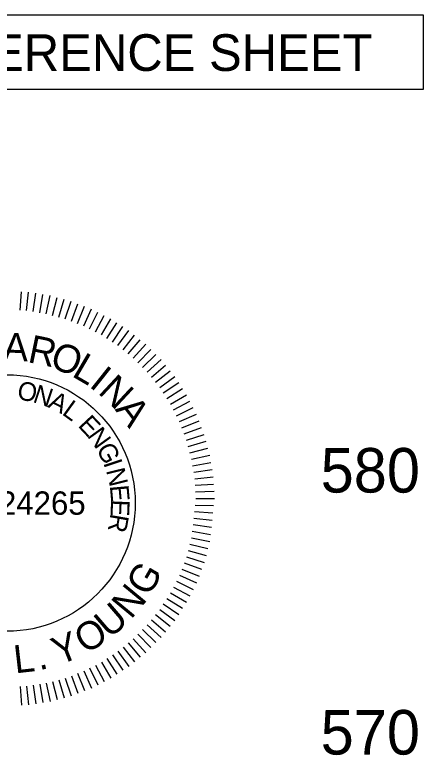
# Model space of a CAD drawing. Extents: x 1964377 to 1966966, y 1116414 to 1123213.
# Drawn here: x 1966872.9 to 1966950.9, y 1122576.7 to 1122718 of the extents above; entities that cross this region are included whole.
import ezdxf

# ---------------------------------------------------------------- set-up
doc = ezdxf.new("R2010")
doc.units = 0
for name, color, linetype in [('RD_DDB_Profile_Elev', 7, 'Continuous'), ('RD_Sketch1', 7, 'Continuous'), ('RD_TX_PEShield', 7, 'Continuous')]:
    doc.layers.add(name, color=color, linetype=linetype)

msp = doc.modelspace()

# ---------------------------------------------------------------- linework, layer by layer
at = {"layer": 'RD_Sketch1'}
msp.add_lwpolyline([(1966650.5, 1122717.98), (1966950.92, 1122717.98), (1966950.92, 1122703.72), (1966650.5, 1122703.72)], close=True, dxfattribs=at)
at = {"layer": 'RD_TX_PEShield'}
for p, q in [((1966873.96, 1122661.59), (1966874.21, 1122665.14)), ((1966873.96, 1122661.59), (1966874.21, 1122665.14)), ((1966875.21, 1122661.52), (1966875.59, 1122665.06)), ((1966875.21, 1122661.52), (1966875.59, 1122665.06)), ((1966876.46, 1122661.33), (1966876.95, 1122664.85)), ((1966876.46, 1122661.33), (1966876.95, 1122664.85)), ((1966877.7, 1122661.13), (1966878.32, 1122664.63)), ((1966877.7, 1122661.13), (1966878.32, 1122664.63)), ((1966878.94, 1122660.93), (1966879.68, 1122664.41)), ((1966878.94, 1122660.93), (1966879.68, 1122664.41)), ((1966878.94, 1122660.93), (1966879.68, 1122664.41)), ((1966880.16, 1122660.61), (1966881.02, 1122664.06)), ((1966880.16, 1122660.61), (1966881.02, 1122664.06)), ((1966880.16, 1122660.61), (1966881.02, 1122664.06)), ((1966881.37, 1122660.28), (1966882.35, 1122663.7)), ((1966881.37, 1122660.28), (1966882.35, 1122663.7)), ((1966881.37, 1122660.28), (1966882.35, 1122663.7)), ((1966882.59, 1122659.96), (1966883.69, 1122663.34)), ((1966882.59, 1122659.96), (1966883.69, 1122663.34)), ((1966882.59, 1122659.96), (1966883.69, 1122663.34)), ((1966883.76, 1122659.51), (1966884.98, 1122662.85)), ((1966883.76, 1122659.51), (1966884.98, 1122662.85)), ((1966883.76, 1122659.51), (1966884.98, 1122662.85)), ((1966884.93, 1122659.06), (1966886.26, 1122662.35)), ((1966884.93, 1122659.06), (1966886.26, 1122662.35)), ((1966884.93, 1122659.06), (1966886.26, 1122662.35)), ((1966886.11, 1122658.6), (1966887.56, 1122661.86)), ((1966886.11, 1122658.6), (1966887.56, 1122661.86)), ((1966886.11, 1122658.6), (1966887.56, 1122661.86)), ((1966887.23, 1122658.03), (1966888.79, 1122661.23)), ((1966887.23, 1122658.03), (1966888.79, 1122661.23)), ((1966887.23, 1122658.03), (1966888.79, 1122661.23)), ((1966888.35, 1122657.46), (1966890.02, 1122660.6)), ((1966888.35, 1122657.46), (1966890.02, 1122660.6)), ((1966888.35, 1122657.46), (1966890.02, 1122660.6)), ((1966889.47, 1122656.89), (1966891.25, 1122659.97)), ((1966889.47, 1122656.89), (1966891.25, 1122659.97)), ((1966889.47, 1122656.89), (1966891.25, 1122659.97)), ((1966890.52, 1122656.21), (1966892.41, 1122659.22)), ((1966890.52, 1122656.21), (1966892.41, 1122659.22)), ((1966890.52, 1122656.21), (1966892.41, 1122659.22)), ((1966891.58, 1122655.52), (1966893.57, 1122658.47)), ((1966891.58, 1122655.52), (1966893.57, 1122658.47)), ((1966891.58, 1122655.52), (1966893.57, 1122658.47)), ((1966892.63, 1122654.84), (1966894.73, 1122657.72)), ((1966892.63, 1122654.84), (1966894.73, 1122657.72)), ((1966892.63, 1122654.84), (1966894.73, 1122657.72)), ((1966893.61, 1122654.04), (1966895.8, 1122656.85)), ((1966893.61, 1122654.04), (1966895.8, 1122656.85)), ((1966893.61, 1122654.04), (1966895.8, 1122656.85)), ((1966894.59, 1122653.25), (1966896.87, 1122655.98)), ((1966894.59, 1122653.25), (1966896.87, 1122655.98)), ((1966894.59, 1122653.25), (1966896.87, 1122655.98)), ((1966895.57, 1122652.46), (1966897.95, 1122655.11)), ((1966895.57, 1122652.46), (1966897.95, 1122655.11)), ((1966895.57, 1122652.46), (1966897.95, 1122655.11)), ((1966896.46, 1122651.57), (1966898.93, 1122654.13)), ((1966896.46, 1122651.57), (1966898.93, 1122654.13)), ((1966896.46, 1122651.57), (1966898.93, 1122654.13)), ((1966897.34, 1122650.68), (1966899.9, 1122653.15)), ((1966897.34, 1122650.68), (1966899.9, 1122653.15)), ((1966897.34, 1122650.68), (1966899.9, 1122653.15)), ((1966898.23, 1122649.79), (1966900.88, 1122652.18)), ((1966898.23, 1122649.79), (1966900.88, 1122652.18)), ((1966898.23, 1122649.79), (1966900.88, 1122652.18)), ((1966899.03, 1122648.82), (1966901.75, 1122651.1)), ((1966899.03, 1122648.82), (1966901.75, 1122651.1)), ((1966899.03, 1122648.82), (1966901.75, 1122651.1)), ((1966899.82, 1122647.84), (1966902.62, 1122650.03)), ((1966899.82, 1122647.84), (1966902.62, 1122650.03)), ((1966899.82, 1122647.84), (1966902.62, 1122650.03)), ((1966900.61, 1122646.86), (1966903.49, 1122648.95)), ((1966900.61, 1122646.86), (1966903.49, 1122648.95)), ((1966900.61, 1122646.86), (1966903.49, 1122648.95)), ((1966901.29, 1122645.81), (1966904.24, 1122647.8)), ((1966901.29, 1122645.81), (1966904.24, 1122647.8)), ((1966901.29, 1122645.81), (1966904.24, 1122647.8)), ((1966901.98, 1122644.75), (1966904.99, 1122646.64)), ((1966901.98, 1122644.75), (1966904.99, 1122646.64)), ((1966901.98, 1122644.75), (1966904.99, 1122646.64)), ((1966902.66, 1122643.7), (1966905.75, 1122645.48)), ((1966902.66, 1122643.7), (1966905.75, 1122645.48)), ((1966902.66, 1122643.7), (1966905.75, 1122645.48)), ((1966903.23, 1122642.58), (1966906.37, 1122644.25)), ((1966903.23, 1122642.58), (1966906.37, 1122644.25)), ((1966903.23, 1122642.58), (1966906.37, 1122644.25)), ((1966903.8, 1122641.46), (1966907, 1122643.02)), ((1966903.8, 1122641.46), (1966907, 1122643.02)), ((1966903.8, 1122641.46), (1966907, 1122643.02)), ((1966904.38, 1122640.34), (1966907.63, 1122641.78)), ((1966904.38, 1122640.34), (1966907.63, 1122641.78)), ((1966904.38, 1122640.34), (1966907.63, 1122641.78)), ((1966904.83, 1122639.16), (1966908.12, 1122640.49)), ((1966904.83, 1122639.16), (1966908.12, 1122640.49)), ((1966904.83, 1122639.16), (1966908.12, 1122640.49)), ((1966905.28, 1122637.99), (1966908.62, 1122639.2)), ((1966905.28, 1122637.99), (1966908.62, 1122639.2)), ((1966905.28, 1122637.99), (1966908.62, 1122639.2)), ((1966905.73, 1122636.81), (1966909.11, 1122637.91)), ((1966905.73, 1122636.81), (1966909.11, 1122637.91)), ((1966905.73, 1122636.81), (1966909.11, 1122637.91)), ((1966906.05, 1122635.6), (1966909.47, 1122636.58)), ((1966906.05, 1122635.6), (1966909.47, 1122636.58)), ((1966906.05, 1122635.6), (1966909.47, 1122636.58)), ((1966906.38, 1122634.38), (1966909.83, 1122635.25)), ((1966906.38, 1122634.38), (1966909.83, 1122635.25)), ((1966906.38, 1122634.38), (1966909.83, 1122635.25)), ((1966906.7, 1122633.17), (1966910.19, 1122633.91)), ((1966906.7, 1122633.17), (1966910.19, 1122633.91)), ((1966906.7, 1122633.17), (1966910.19, 1122633.91)), ((1966906.9, 1122631.93), (1966910.4, 1122632.54)), ((1966906.9, 1122631.93), (1966910.4, 1122632.54)), ((1966906.9, 1122631.93), (1966910.4, 1122632.54)), ((1966907.1, 1122630.69), (1966910.62, 1122631.18)), ((1966907.1, 1122630.69), (1966910.62, 1122631.18)), ((1966907.1, 1122630.69), (1966910.62, 1122631.18)), ((1966907.29, 1122629.44), (1966910.83, 1122629.82)), ((1966907.29, 1122629.44), (1966910.83, 1122629.82)), ((1966907.29, 1122629.44), (1966910.83, 1122629.82)), ((1966907.36, 1122628.19), (1966910.91, 1122628.43)), ((1966907.36, 1122628.19), (1966910.91, 1122628.43)), ((1966907.36, 1122628.19), (1966910.91, 1122628.43)), ((1966907.43, 1122626.93), (1966910.98, 1122627.06)), ((1966907.43, 1122626.93), (1966910.98, 1122627.06)), ((1966907.43, 1122626.93), (1966910.98, 1122627.06)), ((1966907.49, 1122625.68), (1966911.05, 1122625.68)), ((1966907.49, 1122625.68), (1966911.05, 1122625.68)), ((1966907.49, 1122625.68), (1966911.05, 1122625.68)), ((1966907.36, 1122624.42), (1966910.91, 1122624.3)), ((1966907.36, 1122624.42), (1966910.91, 1122624.3)), ((1966907.23, 1122623.17), (1966910.76, 1122622.93)), ((1966907.23, 1122623.17), (1966910.76, 1122622.93)), ((1966906.97, 1122620.68), (1966910.48, 1122620.19)), ((1966906.97, 1122620.68), (1966910.48, 1122620.19)), ((1966907.1, 1122621.93), (1966910.62, 1122621.56)), ((1966907.1, 1122621.93), (1966910.62, 1122621.56)), ((1966906.84, 1122619.44), (1966910.33, 1122618.82)), ((1966906.84, 1122619.44), (1966910.33, 1122618.82)), ((1966906.7, 1122618.18), (1966910.19, 1122617.44)), ((1966906.7, 1122618.18), (1966910.19, 1122617.44)), ((1966906.38, 1122616.97), (1966909.83, 1122616.11)), ((1966906.38, 1122616.97), (1966909.83, 1122616.11)), ((1966906.05, 1122615.75), (1966909.47, 1122614.77)), ((1966906.05, 1122615.75), (1966909.47, 1122614.77)), ((1966905.73, 1122614.54), (1966909.11, 1122613.44)), ((1966905.73, 1122614.54), (1966909.11, 1122613.44)), ((1966904.83, 1122612.19), (1966908.12, 1122610.86)), ((1966904.83, 1122612.19), (1966908.12, 1122610.86)), ((1966905.28, 1122613.36), (1966908.62, 1122612.15)), ((1966905.28, 1122613.36), (1966908.62, 1122612.15)), ((1966904.38, 1122611.01), (1966907.63, 1122609.57)), ((1966904.38, 1122611.01), (1966907.63, 1122609.57)), ((1966903.8, 1122609.89), (1966907, 1122608.33)), ((1966903.8, 1122609.89), (1966907, 1122608.33)), ((1966903.23, 1122608.77), (1966906.37, 1122607.1)), ((1966903.23, 1122608.77), (1966906.37, 1122607.1)), ((1966901.98, 1122606.6), (1966904.99, 1122604.71)), ((1966901.98, 1122606.6), (1966904.99, 1122604.71)), ((1966902.66, 1122607.65), (1966905.75, 1122605.87)), ((1966902.66, 1122607.65), (1966905.75, 1122605.87)), ((1966901.29, 1122605.54), (1966904.24, 1122603.56)), ((1966901.29, 1122605.54), (1966904.24, 1122603.56)), ((1966900.61, 1122604.49), (1966903.49, 1122602.4)), ((1966900.61, 1122604.49), (1966903.49, 1122602.4)), ((1966899.03, 1122602.53), (1966901.75, 1122600.25)), ((1966899.03, 1122602.53), (1966901.75, 1122600.25)), ((1966899.82, 1122603.51), (1966902.62, 1122601.32)), ((1966899.82, 1122603.51), (1966902.62, 1122601.32)), ((1966898.23, 1122601.56), (1966900.88, 1122599.17)), ((1966898.23, 1122601.56), (1966900.88, 1122599.17)), ((1966896.46, 1122599.78), (1966898.93, 1122597.22)), ((1966896.46, 1122599.78), (1966898.93, 1122597.22)), ((1966897.34, 1122600.67), (1966899.9, 1122598.2)), ((1966897.34, 1122600.67), (1966899.9, 1122598.2)), ((1966894.59, 1122598.1), (1966896.87, 1122595.37)), ((1966894.59, 1122598.1), (1966896.87, 1122595.37)), ((1966895.57, 1122598.89), (1966897.95, 1122596.24)), ((1966893.61, 1122597.31), (1966895.8, 1122594.5)), ((1966893.61, 1122597.31), (1966895.8, 1122594.5)), ((1966891.58, 1122595.83), (1966893.57, 1122592.88)), ((1966891.58, 1122595.83), (1966893.57, 1122592.88)), ((1966892.63, 1122596.51), (1966894.73, 1122593.63)), ((1966892.63, 1122596.51), (1966894.73, 1122593.63)), ((1966888.35, 1122593.89), (1966890.02, 1122590.75)), ((1966888.35, 1122593.89), (1966890.02, 1122590.75)), ((1966889.47, 1122594.46), (1966891.25, 1122591.38)), ((1966889.47, 1122594.46), (1966891.25, 1122591.38)), ((1966890.52, 1122595.14), (1966892.41, 1122592.13)), ((1966890.52, 1122595.14), (1966892.41, 1122592.13)), ((1966886.11, 1122592.75), (1966887.56, 1122589.49)), ((1966886.11, 1122592.75), (1966887.56, 1122589.49)), ((1966887.23, 1122593.32), (1966888.79, 1122590.12)), ((1966887.23, 1122593.32), (1966888.79, 1122590.12)), ((1966881.37, 1122591.07), (1966882.35, 1122587.65)), ((1966881.37, 1122591.07), (1966882.35, 1122587.65)), ((1966882.59, 1122591.39), (1966883.69, 1122588.01)), ((1966882.59, 1122591.39), (1966883.69, 1122588.01)), ((1966883.76, 1122591.85), (1966884.98, 1122588.5)), ((1966883.76, 1122591.85), (1966884.98, 1122588.5)), ((1966884.93, 1122592.3), (1966886.26, 1122589)), ((1966884.93, 1122592.3), (1966886.26, 1122589)), ((1966873.96, 1122589.76), (1966874.21, 1122586.22)), ((1966873.96, 1122589.76), (1966874.21, 1122586.22)), ((1966875.21, 1122589.83), (1966875.59, 1122586.29)), ((1966875.21, 1122589.83), (1966875.59, 1122586.29)), ((1966876.46, 1122590.02), (1966876.95, 1122586.5)), ((1966876.46, 1122590.02), (1966876.95, 1122586.5)), ((1966877.7, 1122590.22), (1966878.32, 1122586.72)), ((1966877.7, 1122590.22), (1966878.32, 1122586.72)), ((1966878.94, 1122590.42), (1966879.68, 1122586.94)), ((1966878.94, 1122590.42), (1966879.68, 1122586.94)), ((1966880.16, 1122590.74), (1966881.02, 1122587.29)), ((1966880.16, 1122590.74), (1966881.02, 1122587.29))]:
    msp.add_line(p, q, dxfattribs=at)
msp.add_circle((1966871.45, 1122624.8), 24.48, dxfattribs=at)

# ---------------------------------------------------------------- texts
at = {"layer": 'RD_DDB_Profile_Elev'}
for s, p in [('580', (1966931.34, 1122626.8)), ('570', (1966931.34, 1122576.8))]:
    msp.add_text(s, height=8.5, dxfattribs=at).set_placement(p)
at = {"layer": 'RD_Sketch1'}
msp.add_text('ALIGNMENT CONTROL CAN BE FOUND ON REFERENCE SHEET', height=7, dxfattribs=at).set_placement((1966654.15, 1122707.27))
at = {"layer": 'RD_TX_PEShield'}
for s, height, rotation, p in [('A', 5.34, 357.9448, (1966870.66, 1122651.99)), ('R', 5.34, 348.267, (1966875.24, 1122651.73)), ('O', 5.34, 339.3286, (1966879.38, 1122650.82)), ('L', 5.34, 329.6507, (1966883.64, 1122649.11)), ('I', 5.34, 321.4663, (1966886.98, 1122647.13)), ('N', 5.34, 317.0007, (1966888.67, 1122645.85)), ('O', 3.56, 350.4045, (1966873.25, 1122644.62)), ('N', 3.56, 341.7029, (1966876.22, 1122644.12)), ('A', 3.56, 333.0013, (1966879.09, 1122643.18)), ('L', 3.56, 324.2997, (1966881.79, 1122641.81)), ('A', 5.34, 307.3229, (1966891.96, 1122642.66)), ('E', 3.56, 313.2251, (1966884.86, 1122639.51)), ('N', 3.56, 305.7317, (1966886.66, 1122637.63)), ('G', 3.56, 297.0301, (1966888.43, 1122635.18)), ('I', 3.56, 288.3285, (1966889.81, 1122632.49)), ('N', 3.56, 283.8441, (1966890.35, 1122631.03)), ('E', 3.56, 275.1424, (1966891.08, 1122628.1)), ('E', 3.56, 267.6491, (1966891.34, 1122625.51)), ('R', 3.56, 260.1557, (1966891.26, 1122622.91)), ('G', 5.34, 60.1113, (1966898.56, 1122606.77)), ('N', 5.34, 50.4335, (1966895.14, 1122602.47)), ('U', 5.34, 40.7556, (1966891.05, 1122598.81)), ('O', 5.34, 31.0778, (1966886.4, 1122595.88)), ('Y', 5.34, 21.4, (1966881.33, 1122593.78)), ('L', 5.34, 6.5171, (1966873.03, 1122592.28)), ('.', 5.34, 14.7016, (1966877.64, 1122592.84))]:
    msp.add_text(s, height=height, rotation=rotation, dxfattribs=at).set_placement(p)
msp.add_text('NO. 24265', height=4.45, dxfattribs=at).set_placement((1966857.69, 1122622.57))

doc.saveas('drawing.dxf')
